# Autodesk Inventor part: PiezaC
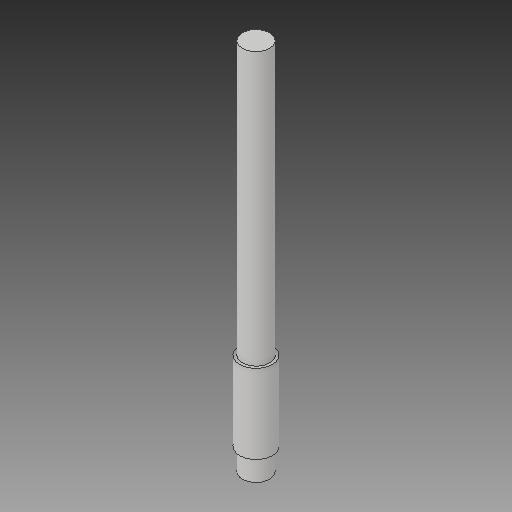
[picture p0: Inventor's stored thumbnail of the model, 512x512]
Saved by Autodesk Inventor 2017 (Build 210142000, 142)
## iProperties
Part Number: PiezaC
Material: Genérico
Document SubType Name: Modeling
Designer: Jaime
Density: 1 g/cm^3
Appearance: Valor por defecto
Mass: 11.7621 g
Surface Area: 47.1239 cm^2
Volume: 11.7621 cm^3
Author: Jaime
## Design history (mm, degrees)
sketch "Boceto1"
  geometry: C1 r 5 at (0, 0); 1 further point
  constraints: 1 centre point, 1 coincident
  dimensions: "d0" = 10 diameter of C1
extrude "Extrusión1" new body sketch "Boceto1" distance "d1" = 8; taper "d2" = 0 deg
sketch "Boceto2"
  geometry: C1 r 6 at (0, 0); 2 further points
  constraints: 1 centre point, 1 coincident, 1 horizontal alignment
  dimensions: "d13" = 12 diameter of C1
extrude "Extrusión2" join sketch "Boceto2" distance "d4" = 29; taper "d5" = 0 deg
sketch "Boceto3"
  geometry: C1 r 5 at (0, 0); 1 further point
  constraints: 1 centre point, 1 coincident
  dimensions: "d10" = 10 diameter of C1
extrude "Extrusión3" join sketch "Boceto3" distance "d11" = 100; taper "d12" = 0 deg
node "Sólido1"
